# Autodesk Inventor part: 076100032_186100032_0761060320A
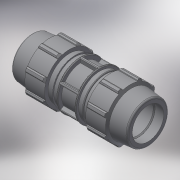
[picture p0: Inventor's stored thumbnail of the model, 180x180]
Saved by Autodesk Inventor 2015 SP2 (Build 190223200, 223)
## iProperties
Created: 2017-02
Part Number: 076100032_186100032_0761060320A
Material: Generic
Description: PLASSON REPAIR COUPLER 32
Document SubType Name: Modeling
Designer: KIM
Mass: 270.586 g
Surface Area: 592.214 cm^2
Volume: 270.586 cm^3
Density: 1 g/cm^3
Appearance: Default
Author: KIM
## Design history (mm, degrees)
derived "07610.ipt"
feature "Solid1::07610.ipt"
tag "TaggingFeature1"
body "Solid1"
other parameters: "d1" = 174, "d2" = 32, "d4" = 14.5, "d5" = 24.85714, "d7" = 64, "d8" = 48, "d9" = 24.85714, "d11" = 3.48571, "d12" = 51.2, "d13" = 120 deg, "d14" = 48, "d15" = 10 deg, "d16" = 57.6, "d18" = 1.6, "d19" = 35 deg, "d20" = 17.5 deg, "d21" = 59.52, "d23" = 0, "d25" = 360 deg, "d27" = 1.28, "d33" = 0.64, "d34" = 3.2, "d36" = 0, "d37" = 0.64, "d38" = 0.64, "d40" = 360 deg, "d42" = 31.32, "d43" = 1.92, "d46" = 0.96, "d50" = 6.21143, "d51" = 51.2, "d_" = 32, "E_" = 64, "H_" = 174, "d49" = 15.90857
